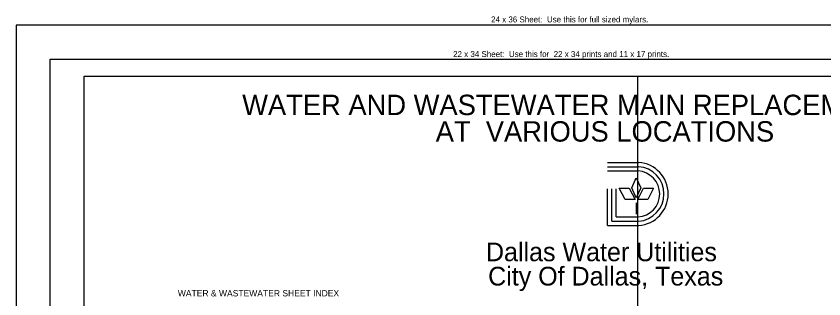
# Model space of a CAD drawing. Extents: x 105094 to 105814, y -291615 to -291123.
# Drawn here: x 105094.1 to 105568.6, y -291289.2 to -291123.1 of the extents above; entities that cross this region are included whole.
import ezdxf

# ---------------------------------------------------------------- set-up
doc = ezdxf.new("R2010")
doc.units = 0
for name, color, linetype in [('G_BORDER', 7, 'Continuous'), ('G_LOGO', 7, 'Continuous'), ('G_SHEET_EDGE', 7, 'Continuous')]:
    doc.layers.add(name, color=color, linetype=linetype)

msp = doc.modelspace()

# ---------------------------------------------------------------- linework, layer by layer
at = {"layer": 'G_BORDER'}
msp.add_line((105459.14, -291158.4), (105459.14, -291578.4), dxfattribs=at)
msp.add_lwpolyline([(105134.14, -291158.4), (105784.14, -291158.4), (105784.14, -291578.4), (105134.14, -291578.4)], close=True, dxfattribs=at)
at = {"layer": 'G_LOGO'}
for p, q in [((105441.59, -291209.05), (105459.89, -291209.05)), ((105441.59, -291211.56), (105459.73, -291211.56)), ((105441.59, -291214.07), (105459.56, -291214.07)), ((105455.89, -291223.98), (105458.47, -291218.07)), ((105458.47, -291218.07), (105461.06, -291223.98)), ((105441.59, -291246.11), (105441.59, -291224.52)), ((105444.1, -291243.61), (105444.1, -291224.52)), ((105446.61, -291241.1), (105446.61, -291224.52)), ((105448.42, -291224.11), (105454.31, -291224.11)), ((105451.83, -291230.86), (105448.42, -291224.11)), ((105454.31, -291224.11), (105457.73, -291230.86)), ((105458.47, -291229.88), (105455.89, -291223.98)), ((105461.06, -291223.98), (105458.47, -291229.88)), ((105459.33, -291230.86), (105462.75, -291224.11)), ((105462.75, -291224.11), (105468.64, -291224.11)), ((105468.64, -291224.11), (105465.23, -291230.86)), ((105457.73, -291230.86), (105451.83, -291230.86)), ((105465.23, -291230.86), (105459.33, -291230.86)), ((105458.59, -291239.56), (105458.59, -291232.88)), ((105446.61, -291241.1), (105459.56, -291241.1)), ((105441.59, -291246.11), (105459.89, -291246.11)), ((105444.1, -291243.61), (105459.73, -291243.61))]:
    msp.add_line(p, q, dxfattribs=at)
for radius in [16.06, 18.56, 13.55]:
    msp.add_arc((105458.66, -291227.59), radius, 273.8202, 86.1798, dxfattribs=at)
at = {"layer": 'G_SHEET_EDGE'}
for points in [[(105094.14, -291608.4), (105814.14, -291608.4), (105814.14, -291128.4), (105094.14, -291128.4)], [(105114.14, -291148.4), (105794.14, -291148.4), (105794.14, -291588.4), (105114.14, -291588.4)]]:
    msp.add_lwpolyline(points, close=True, dxfattribs=at)

# ---------------------------------------------------------------- texts
at = {"layer": 'G_BORDER'}
for s, height, p in [('WATER AND WASTEWATER MAIN REPLACEMENTS', 12, (105226.93, -291181.27)), ('AT  VARIOUS LOCATIONS', 12, (105340.63, -291196.83)), ('Dallas Water Utilities', 11, (105370.14, -291267.13)), ('City Of Dallas, Texas', 11, (105371.41, -291281.4)), ('WATER & WASTEWATER SHEET INDEX', 3.7405, (105189.12, -291287.81))]:
    msp.add_text(s, height=height, dxfattribs=at).set_placement(p)
at = {"layer": 'G_SHEET_EDGE'}
for s, p in [('24 x 36 Sheet:  Use this for full sized mylars. ', (105373.17, -291126.79)), ('22 x 34 Sheet:  Use this for  22 x 34 prints and 11 x 17 prints. ', (105350.86, -291147.14))]:
    msp.add_text(s, height=3.5, dxfattribs=at).set_placement(p)

doc.saveas('drawing.dxf')
